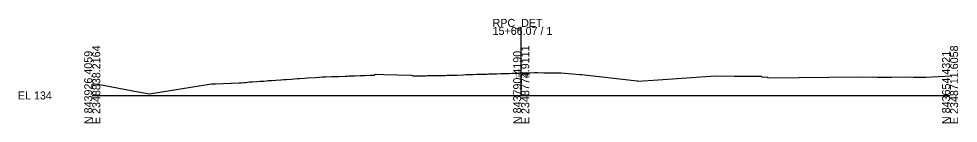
# Model space of a CAD drawing. Extents: x -26 to 2348728, y -10 to 843971.
# Drawn here: x -25.7 to 302.8, y 6990.3 to 7026.8 of the extents above; entities that cross this region are included whole.
import ezdxf

# ---------------------------------------------------------------- set-up
doc = ezdxf.new("R2010")
doc.units = 0
for name, color, linetype in [('Exist Cross Section Cell', 7, 'Continuous'), ('Exist XS Center Line Elevation Label', 7, 'Continuous'), ('Exist XS Ground Line', 7, 'Continuous')]:
    doc.layers.add(name, color=color, linetype=linetype)

msp = doc.modelspace()

# ---------------------------------------------------------------- linework, layer by layer
at = {"layer": 'Exist Cross Section Cell'}
for p, q in [((150, 7000), (150, 7023.97)), ((0, 7000), (150, 7000)), ((150, 7000), (300, 7000))]:
    msp.add_line(p, q, dxfattribs=at)
at = {"layer": 'Exist XS Ground Line'}
msp.add_lwpolyline([(0, 7004.12), (1.93, 7003.93), (16.04, 7001.24), (20.04, 7000.59), (38.07, 7003.48), (40.27, 7003.83), (41.73, 7004.06), (42.74, 7004.11), (43.05, 7004.12), (51.37, 7004.44), (51.79, 7004.46), (52.21, 7004.48), (53.15, 7004.55), (53.62, 7004.59), (54.95, 7004.72), (55.97, 7004.77), (57.52, 7004.88), (58.68, 7004.96), (60, 7005.06), (60.99, 7005.14), (61.47, 7005.18), (62.88, 7005.28), (64.23, 7005.37), (65.95, 7005.49), (66.98, 7005.56), (67.86, 7005.63), (69.72, 7005.76), (71.82, 7005.9), (72.47, 7005.95), (74.17, 7006.06), (75.25, 7006.14), (78.05, 7006.33), (79.44, 7006.43), (80.38, 7006.47), (80.77, 7006.48), (81.63, 7006.52), (83.68, 7006.59), (85.44, 7006.66), (86.26, 7006.69), (88.46, 7006.78), (89.2, 7006.81), (89.63, 7006.82), (91.09, 7006.87), (91.79, 7006.89), (93.75, 7006.96), (94.84, 7007), (95.47, 7007.02), (97.23, 7007.08), (98.13, 7007.12), (98.45, 7007.15), (99.02, 7007.43), (102, 7007.36), (111.56, 7007.11), (112.26, 7006.86), (113.93, 7006.88), (114.38, 7006.88), (116.61, 7006.92), (117.41, 7006.94), (119.35, 7006.99), (121.19, 7007.02), (122.14, 7007.03), (123.39, 7007.04), (124.13, 7007.05), (124.89, 7007.07), (125.21, 7007.08), (126.88, 7007.13), (127.64, 7007.16), (129.79, 7007.25), (130.62, 7007.29), (131.09, 7007.3), (133.17, 7007.36), (134.35, 7007.4), (135.62, 7007.43), (135.96, 7007.44), (137.04, 7007.48), (138.14, 7007.51), (138.67, 7007.52), (140.04, 7007.55), (141.41, 7007.62), (142.93, 7007.68), (143.78, 7007.71), (144.17, 7007.72), (145.69, 7007.74), (146.9, 7007.78), (148.84, 7007.86), (149.67, 7007.88), (150, 7007.89), (151.27, 7007.91), (152.43, 7007.94), (153.16, 7007.96), (154.66, 7007.98), (155.22, 7007.99), (155.72, 7007.99), (157.96, 7007.97), (160.18, 7007.96), (160.65, 7007.97), (162.65, 7007.94), (163.17, 7007.96), (164, 7007.97), (170.47, 7007.34), (171.11, 7007.28), (190.54, 7005.09), (190.84, 7005.05), (197.87, 7005.49), (212.88, 7006.53), (216.29, 7006.8), (218.13, 7006.84), (224.44, 7006.8), (233.95, 7006.77), (234.33, 7006.49), (236, 7006.45), (236.1, 7006.25), (236.5, 7006.22), (247.27, 7006.3), (267.92, 7006.54), (272.94, 7006.46), (273.45, 7006.47), (274.51, 7006.45), (279.17, 7006.35), (279.6, 7006.35), (285.2, 7006.55), (287.23, 7006.42), (288.45, 7006.36), (290.22, 7006.37), (291.49, 7006.41), (298.16, 7006.8), (300, 7006.82)], dxfattribs=at)

# ---------------------------------------------------------------- texts
at = {"layer": 'Exist Cross Section Cell'}
for s, p in [('15+66.07 / 1', (140, 7021.17)), ('RPC_DET', (140, 7023.97)), ('EL 134', (-26, 6998.6))]:
    msp.add_text(s, height=2.8, dxfattribs=at).set_placement(p)
for s, p in [('N 843926.4059', (0, 6990)), ('E 2348838.2164', (2.8, 6990)), ('N 843790.4190', (150, 6990)), ('E 2348774.9111', (152.8, 6990)), ('N 843654.4321', (300, 6990)), ('E 2348711.6058', (302.8, 6990))]:
    msp.add_text(s, height=2.8, rotation=90, dxfattribs=at).set_placement(p)
at = {"layer": 'Exist XS Center Line Elevation Label'}
msp.add_text('141.89', height=1.2, dxfattribs=at).set_placement((147.89, 7006.29))

doc.saveas('drawing.dxf')
